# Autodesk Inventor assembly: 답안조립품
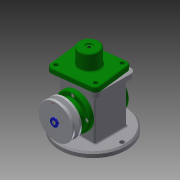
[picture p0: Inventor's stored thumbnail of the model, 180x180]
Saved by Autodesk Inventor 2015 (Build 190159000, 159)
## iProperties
Created: 2019-08
Part Number: 답안조립품
Document SubType Name: Assembly
Designer: now
Author: now
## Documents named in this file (18)
- C:\Users\now\Desktop\490804V1031\답안조립품.iam
- C:\Users\now\Desktop\490804V1031\E-링.ipt
- C:\Users\now\Desktop\490804V1031\V-벨트풀리.ipt
- C:\Users\now\Desktop\490804V1031\덮개.ipt
- C:\Users\now\Desktop\490804V1031\뒤커버.ipt
- C:\Users\now\Desktop\490804V1031\링크.ipt
- C:\Users\now\Desktop\490804V1031\베어링 17 x 40 x 12.ipt
- C:\Users\now\Desktop\490804V1031\본체.ipt
- C:\Users\now\Desktop\490804V1031\볼트 M4 x 8.ipt
- C:\Users\now\Desktop\490804V1031\볼트 M4 x 10.ipt
- C:\Users\now\Desktop\490804V1031\슬라이더.ipt
- C:\Users\now\Desktop\490804V1031\앞커버.ipt
- C:\Users\now\Desktop\490804V1031\오일 실 17 30 8.ipt
- C:\Users\now\Desktop\490804V1031\와셔 4x16.ipt
- C:\Users\now\Desktop\490804V1031\클레비스 핀 6 x 22.ipt
- 클레비스 핀 6 x 22.ipt
- C:\Users\now\Desktop\490804V1031\키 4 x 4 x 12.ipt
- C:\Users\now\Desktop\490804V1031\편심축.ipt
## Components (2 placed, 2 different names)
1. E-링:1
2. V-벨트풀리:1 — 각도:2
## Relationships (1: Angle 1)
- 각도:2 [Angle]: V-벨트풀리:1
